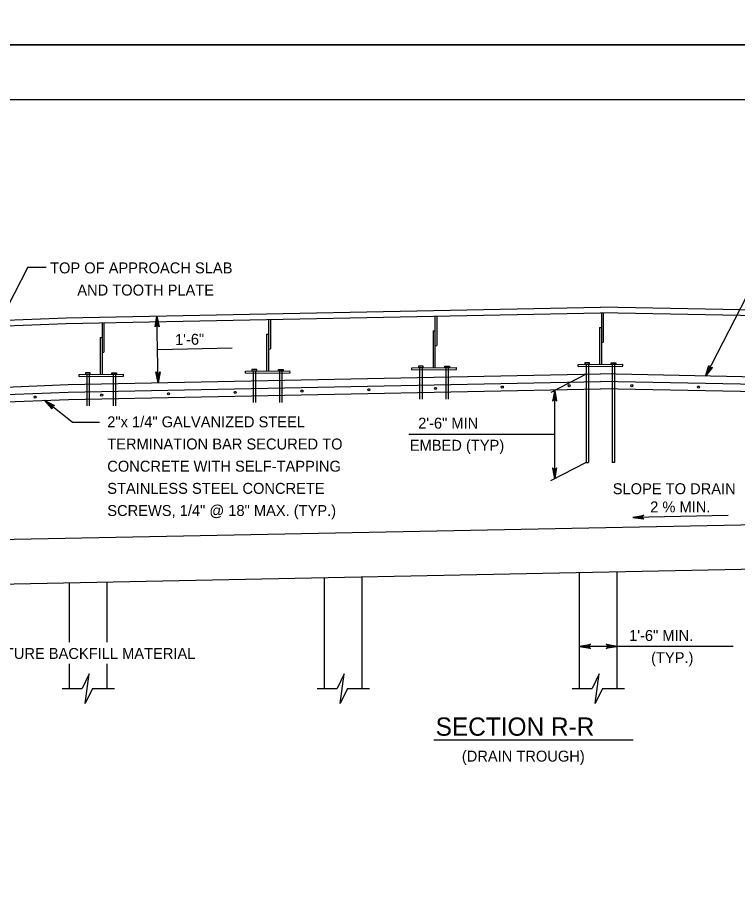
# Model space of a CAD drawing. Extents: x 636530 to 644067, y 294168 to 299122.
# Drawn here: x 638388.9 to 638586, y 294528.9 to 294770 of the extents above; entities that cross this region are included whole.
import ezdxf

# ---------------------------------------------------------------- set-up
doc = ezdxf.new("R2010")
doc.units = 0
doc.layers.add('1', color=7, linetype='Continuous')
doc.layers.add('PLT-BNDY', color=7, linetype='Continuous')

msp = doc.modelspace()

# ---------------------------------------------------------------- linework, layer by layer
at = {"layer": '1'}
for p, q in [((638991.78, 294747.48), (638205.78, 294747.48)), ((638600.6, 294717.27), (638577.27, 294671.77)), ((638391.68, 294701.56), (638384.21, 294686.99)), ((638391.68, 294701.56), (638396.74, 294701.56)), ((638402.16, 294687.71), (638548.46, 294690.64)), ((638402.2, 294686.19), (638548.46, 294689.11)), ((638694.77, 294687.71), (638548.46, 294690.64)), ((638694.72, 294686.19), (638548.46, 294689.11)), ((638548.72, 294689.12), (638548.72, 294674.97)), ((638549.22, 294689.14), (638549.22, 294681.01)), ((638300.56, 294683.65), (638402.16, 294687.71)), ((638427.38, 294669.92), (638427.01, 294688.21)), ((638457.58, 294687.3), (638457.58, 294673.14)), ((638458.09, 294687.32), (638458.09, 294679.19)), ((638503.15, 294688.21), (638503.15, 294674.05)), ((638503.65, 294688.23), (638503.65, 294680.1)), ((638300.62, 294682.13), (638402.2, 294686.19)), ((638412.01, 294686.39), (638412.01, 294672.23)), ((638412.52, 294686.41), (638412.52, 294678.28)), ((638502.64, 294684.12), (638503.15, 294684.15)), ((638502.64, 294684.12), (638502.64, 294674.05)), ((638548.21, 294685.04), (638548.72, 294685.06)), ((638548.21, 294685.04), (638548.21, 294674.96)), ((638411.51, 294682.3), (638412.01, 294682.32)), ((638411.51, 294682.3), (638411.51, 294672.23)), ((638457.07, 294683.21), (638457.58, 294683.23)), ((638457.07, 294683.21), (638457.07, 294673.14)), ((638427.2, 294679.07), (638447.65, 294679.48)), ((638503.15, 294680.08), (638503.65, 294680.1)), ((638548.72, 294680.99), (638549.22, 294681.01)), ((638412.01, 294678.26), (638412.52, 294678.28)), ((638457.58, 294679.17), (638458.09, 294679.19)), ((638542.4, 294674.92), (638554.6, 294675.01)), ((638542.41, 294674.41), (638542.4, 294674.92)), ((638542.41, 294674.41), (638554.6, 294674.5)), ((638544.52, 294675), (638544.52, 294648.05)), ((638545.17, 294675), (638545.17, 294648.05)), ((638551.71, 294675), (638551.71, 294648.05)), ((638552.36, 294675), (638552.36, 294648.05)), ((638554.6, 294674.5), (638554.6, 294675.01)), ((638402.69, 294669.43), (638548.46, 294672.35)), ((638405.7, 294672.18), (638417.89, 294672.28)), ((638405.7, 294671.68), (638405.7, 294672.18)), ((638407.82, 294672.27), (638407.82, 294663.6)), ((638408.47, 294672.27), (638408.47, 294663.6)), ((638415.01, 294672.27), (638415.01, 294663.6)), ((638415.66, 294672.27), (638415.66, 294663.6)), ((638417.9, 294671.77), (638417.89, 294672.28)), ((638451.27, 294673.1), (638463.46, 294673.19)), ((638451.27, 294672.59), (638451.27, 294673.1)), ((638451.27, 294672.59), (638463.47, 294672.68)), ((638453.39, 294673.18), (638453.39, 294664.51)), ((638454.04, 294673.18), (638454.04, 294664.51)), ((638460.58, 294673.18), (638460.58, 294664.51)), ((638461.23, 294673.18), (638461.23, 294664.51)), ((638463.47, 294672.68), (638463.46, 294673.19)), ((638496.84, 294674.01), (638509.03, 294674.1)), ((638496.84, 294673.5), (638496.84, 294674.01)), ((638496.84, 294673.5), (638509.03, 294673.59)), ((638498.96, 294674.09), (638498.96, 294665.43)), ((638499.61, 294674.09), (638499.61, 294665.43)), ((638506.15, 294674.09), (638506.15, 294665.43)), ((638506.8, 294674.09), (638506.8, 294665.43)), ((638509.03, 294673.59), (638509.03, 294674.1)), ((638544.52, 294672.27), (638534.88, 294667.3)), ((638694.24, 294669.43), (638548.46, 294672.35)), ((638402.75, 294667.4), (638548.46, 294670.31)), ((638405.7, 294671.68), (638417.9, 294671.77)), ((638694.2, 294667.4), (638548.46, 294670.31)), ((638300.93, 294663.33), (638402.75, 294667.4)), ((638304.62, 294665.51), (638402.69, 294669.43)), ((638402.81, 294665.37), (638548.46, 294668.28)), ((638535.94, 294643.62), (638535.94, 294667.84)), ((638694.16, 294665.37), (638548.46, 294668.28)), ((638306.47, 294661.51), (638402.81, 294665.37)), ((638403.79, 294659.13), (638396.32, 294665.11)), ((638403.79, 294659.13), (638411.28, 294659.13)), ((638544.52, 294648.05), (638534.83, 294643.05)), ((638544.52, 294648.05), (638545.17, 294648.05)), ((638552.36, 294648.05), (638551.71, 294648.05)), ((638792.3, 294635.04), (638304.62, 294625.29)), ((638583.44, 294633.58), (638557.34, 294633.05)), ((638792.3, 294622.85), (638304.62, 294613.09)), ((638483.24, 294586.21), (638483.24, 294616.67)), ((638542.74, 294586.21), (638542.74, 294617.86)), ((638553.05, 294586.21), (638553.05, 294618.06)), ((638403.11, 294598.84), (638403.11, 294615.06)), ((638413.42, 294598.84), (638413.42, 294615.27)), ((638472.93, 294586.21), (638472.93, 294616.46)), ((638584.84, 294597.72), (638542.74, 294597.72)), ((638403.11, 294586.21), (638403.11, 294592.92)), ((638413.42, 294586.21), (638413.42, 294592.92)), ((638401.08, 294586.21), (638406.57, 294586.21)), ((638409.38, 294586.21), (638415.44, 294586.21)), ((638470.89, 294586.21), (638476.38, 294586.21)), ((638479.2, 294586.21), (638485.25, 294586.21)), ((638540.71, 294586.21), (638546.2, 294586.21)), ((638549.01, 294586.21), (638555.06, 294586.21)), ((638502.83, 294572.12), (638557.44, 294572.12))]:
    msp.add_line(p, q, dxfattribs=at)
for points in [[(638427.01, 294688.21), (638427.63, 294685.24), (638427.47, 294685.46), (638427.27, 294685.58), (638427.07, 294685.61), (638426.87, 294685.57), (638426.67, 294685.45), (638426.51, 294685.22), (638427.01, 294688.21), (638426.67, 294685.45), (638426.87, 294685.57), (638427.01, 294688.21), (638427.07, 294685.61), (638427.27, 294685.58), (638427.01, 294688.21), (638427.47, 294685.46)], [(638577.27, 294671.77), (638578.13, 294674.68), (638578.15, 294674.54), (638578.17, 294674.4), (638578.23, 294674.3), (638578.29, 294674.21), (638578.37, 294674.14), (638578.45, 294674.08), (638578.55, 294674.05), (638578.65, 294674.02), (638578.76, 294674.03), (638578.88, 294674.04), (638579, 294674.1), (638579.12, 294674.17), (638577.27, 294671.77), (638579, 294674.1), (638578.88, 294674.04), (638577.27, 294671.77), (638578.76, 294674.03), (638578.65, 294674.02), (638577.27, 294671.77), (638578.55, 294674.05), (638578.45, 294674.08), (638577.27, 294671.77), (638578.37, 294674.14), (638578.29, 294674.21), (638577.27, 294671.77), (638578.23, 294674.3), (638578.17, 294674.4), (638577.27, 294671.77), (638578.15, 294674.54)], [(638427.38, 294669.92), (638426.76, 294672.9), (638426.92, 294672.67), (638427.13, 294672.55), (638427.33, 294672.52), (638427.53, 294672.56), (638427.72, 294672.68), (638427.88, 294672.92), (638427.38, 294669.92), (638427.72, 294672.68), (638427.53, 294672.56), (638427.38, 294669.92), (638427.33, 294672.52), (638427.13, 294672.55), (638427.38, 294669.92), (638426.92, 294672.67)], [(638535.94, 294667.84), (638535.38, 294664.86), (638535.46, 294664.97), (638535.54, 294665.09), (638535.64, 294665.15), (638535.74, 294665.21), (638535.84, 294665.23), (638535.94, 294665.24), (638536.04, 294665.23), (638536.14, 294665.21), (638536.24, 294665.15), (638536.34, 294665.09), (638536.42, 294664.97), (638536.5, 294664.86), (638535.94, 294667.84), (638536.42, 294664.97), (638536.34, 294665.09), (638535.94, 294667.84), (638536.24, 294665.15), (638536.14, 294665.21), (638535.94, 294667.84), (638536.04, 294665.23), (638535.94, 294665.24), (638535.94, 294667.84), (638535.84, 294665.23), (638535.74, 294665.21), (638535.94, 294667.84), (638535.64, 294665.15), (638535.54, 294665.09), (638535.94, 294667.84), (638535.46, 294664.97)], [(638396.32, 294665.11), (638398.99, 294663.68), (638398.86, 294663.69), (638398.72, 294663.7), (638398.61, 294663.66), (638398.5, 294663.62), (638398.42, 294663.55), (638398.35, 294663.49), (638398.3, 294663.4), (638398.25, 294663.31), (638398.23, 294663.19), (638398.22, 294663.08), (638398.26, 294662.94), (638398.3, 294662.81), (638396.32, 294665.11), (638398.26, 294662.94), (638398.22, 294663.08), (638396.32, 294665.11), (638398.23, 294663.19), (638398.25, 294663.31), (638396.32, 294665.11), (638398.3, 294663.4), (638398.35, 294663.49), (638396.32, 294665.11), (638398.42, 294663.55), (638398.5, 294663.62), (638396.32, 294665.11), (638398.61, 294663.66), (638398.72, 294663.7), (638396.32, 294665.11), (638398.86, 294663.69)], [(638535.94, 294655.73), (638495.96, 294655.73)], [(638535.94, 294643.62), (638536.5, 294646.6), (638536.42, 294646.49), (638536.34, 294646.37), (638536.24, 294646.31), (638536.14, 294646.25), (638536.04, 294646.24), (638535.94, 294646.22), (638535.84, 294646.24), (638535.74, 294646.25), (638535.64, 294646.31), (638535.54, 294646.37), (638535.46, 294646.49), (638535.38, 294646.6), (638535.94, 294643.62), (638535.46, 294646.49), (638535.54, 294646.37), (638535.94, 294643.62), (638535.64, 294646.31), (638535.74, 294646.25), (638535.94, 294643.62), (638535.84, 294646.24), (638535.94, 294646.22), (638535.94, 294643.62), (638536.04, 294646.24), (638536.14, 294646.25), (638535.94, 294643.62), (638536.24, 294646.31), (638536.34, 294646.37), (638535.94, 294643.62), (638536.42, 294646.49)], [(638557.34, 294633.05), (638560.31, 294633.67), (638560.2, 294633.59), (638560.08, 294633.51), (638560.03, 294633.41), (638559.97, 294633.31), (638559.95, 294633.21), (638559.94, 294633.11), (638559.96, 294633.01), (638559.98, 294632.91), (638560.04, 294632.81), (638560.1, 294632.71), (638560.22, 294632.63), (638560.33, 294632.55), (638557.34, 294633.05), (638560.22, 294632.63), (638560.1, 294632.71), (638557.34, 294633.05), (638560.04, 294632.81), (638559.98, 294632.91), (638557.34, 294633.05), (638559.96, 294633.01), (638559.94, 294633.11), (638557.34, 294633.05), (638559.95, 294633.21), (638559.97, 294633.31), (638557.34, 294633.05), (638560.03, 294633.41), (638560.08, 294633.51), (638557.34, 294633.05), (638560.2, 294633.59)], [(638542.74, 294597.72), (638545.72, 294598.28), (638545.61, 294598.2), (638545.49, 294598.12), (638545.43, 294598.02), (638545.37, 294597.92), (638545.36, 294597.82), (638545.34, 294597.72), (638545.36, 294597.62), (638545.37, 294597.52), (638545.43, 294597.42), (638545.49, 294597.32), (638545.61, 294597.24), (638545.72, 294597.16), (638542.74, 294597.72), (638545.61, 294597.24), (638545.49, 294597.32), (638542.74, 294597.72), (638545.43, 294597.42), (638545.37, 294597.52), (638542.74, 294597.72), (638545.36, 294597.62), (638545.34, 294597.72), (638542.74, 294597.72), (638545.36, 294597.82), (638545.37, 294597.92), (638542.74, 294597.72), (638545.43, 294598.02), (638545.49, 294598.12), (638542.74, 294597.72), (638545.61, 294598.2)], [(638553.05, 294597.72), (638550.07, 294597.16), (638550.18, 294597.24), (638550.3, 294597.32), (638550.36, 294597.42), (638550.42, 294597.52), (638550.43, 294597.62), (638550.45, 294597.72), (638550.43, 294597.82), (638550.42, 294597.92), (638550.36, 294598.02), (638550.3, 294598.12), (638550.18, 294598.2), (638550.07, 294598.28), (638553.05, 294597.72), (638550.18, 294598.2), (638550.3, 294598.12), (638553.05, 294597.72), (638550.36, 294598.02), (638550.42, 294597.92), (638553.05, 294597.72), (638550.43, 294597.82), (638550.45, 294597.72), (638553.05, 294597.72), (638550.43, 294597.62), (638550.42, 294597.52), (638553.05, 294597.72), (638550.36, 294597.42), (638550.3, 294597.32), (638553.05, 294597.72), (638550.18, 294597.24)], [(638409.38, 294586.21), (638407.35, 294582.06), (638408.46, 294590.18), (638406.57, 294586.21)], [(638479.2, 294586.21), (638477.17, 294582.06), (638478.27, 294590.18), (638476.38, 294586.21)], [(638549.01, 294586.21), (638546.98, 294582.06), (638548.09, 294590.18), (638546.2, 294586.21)]]:
    msp.add_lwpolyline(points, dxfattribs=at)
for points in [[(638498.62, 294674.09), (638499.9, 294674.09), (638499.9, 294674.51), (638498.62, 294674.51)], [(638507.13, 294674.09), (638505.85, 294674.09), (638505.85, 294674.51), (638507.13, 294674.51)], [(638544.19, 294675), (638545.47, 294675), (638545.47, 294675.42), (638544.19, 294675.42)], [(638552.7, 294675), (638551.42, 294675), (638551.42, 294675.42), (638552.7, 294675.42)], [(638407.48, 294672.27), (638408.77, 294672.27), (638408.77, 294672.69), (638407.48, 294672.69)], [(638416, 294672.27), (638414.71, 294672.27), (638414.71, 294672.69), (638416, 294672.69)], [(638453.05, 294673.18), (638454.34, 294673.18), (638454.34, 294673.6), (638453.05, 294673.6)], [(638461.56, 294673.18), (638460.28, 294673.18), (638460.28, 294673.6), (638461.56, 294673.6)]]:
    msp.add_lwpolyline(points, close=True, dxfattribs=at)
for centre in [(638430.17, 294666.93), (638448.46, 294667.3), (638466.74, 294667.66), (638485.03, 294668.03), (638503.31, 294668.39), (638521.59, 294668.76), (638539.88, 294669.13), (638557.04, 294669.13), (638575.33, 294668.76), (638393.71, 294666.02), (638411.89, 294666.57)]:
    msp.add_circle(centre, 0.281, dxfattribs=at)
at = {"layer": 'PLT-BNDY'}
for points in [[(638165.78, 295356.48), (639006.78, 295356.48), (639006.78, 294762.48), (638165.78, 294762.48)], [(638165.78, 294762.48), (639006.78, 294762.48), (639006.78, 294168.48), (638165.78, 294168.48)]]:
    msp.add_lwpolyline(points, close=True, dxfattribs=at)

# ---------------------------------------------------------------- texts
at = {"layer": '1'}
for s, height, p in [('TOP OF APPROACH SLAB', 3, (638397.77, 294699.9)), ('AND TOOTH PLATE', 3, (638405.22, 294693.82)), ('2"x 1/4" GALVANIZED STEEL', 3, (638413.43, 294657.72)), ('TERMINATION BAR SECURED TO', 3, (638413.43, 294651.65)), ('CONCRETE WITH SELF-TAPPING', 3, (638413.43, 294645.57)), ('STAINLESS STEEL CONCRETE', 3, (638413.43, 294639.5)), ('SLOPE TO DRAIN', 3, (638551.84, 294639.4)), ('SCREWS, 1/4" @ 18" MAX. (TYP.)', 3, (638413.43, 294633.43)), ('2 % MIN.', 3, (638562.09, 294634.41)), ('1\'-6" MIN.', 3, (638556.32, 294599.19)), ('STRUCTURE BACKFILL MATERIAL', 3, (638371.57, 294594.27)), ('(TYP.)', 3, (638562.34, 294593.12)), ('SECTION R-R', 5, (638503.34, 294573.23)), ('(DRAIN TROUGH)', 3, (638510.52, 294566.14))]:
    msp.add_text(s, height=height, dxfattribs=at).set_placement(p)
for s, rotation, p in [('1\'-6"', 1.1458, (638432.02, 294680.24)), ('2\'-6" MIN', 360, (638498.55, 294657.37)), ('EMBED (TYP)', 360, (638496.27, 294651.3))]:
    msp.add_text(s, height=3, rotation=rotation, dxfattribs=at).set_placement(p)

doc.saveas('drawing.dxf')
